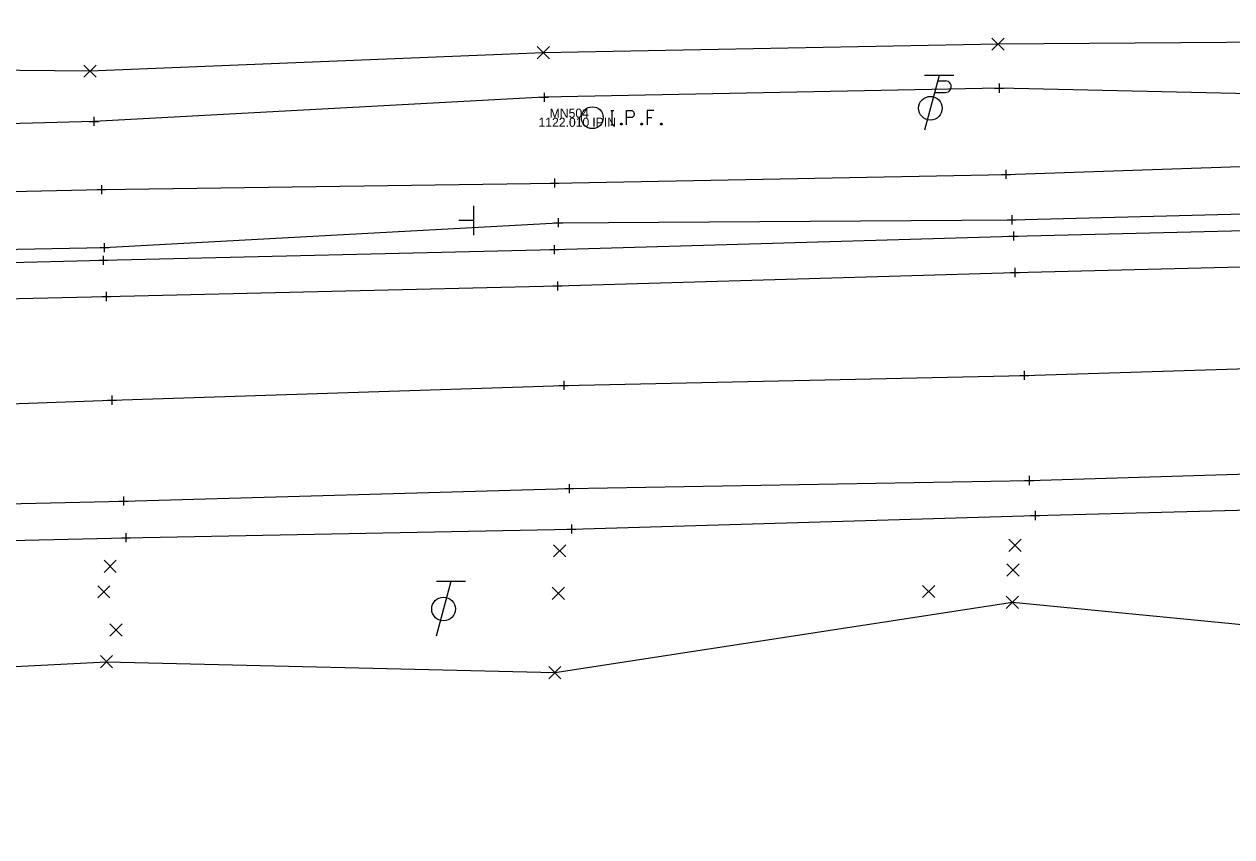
# Model space of a CAD drawing. Extents: x 2402028 to 2407435, y 498611 to 499105.
# Drawn here: x 2403678 to 2403810.6, y 498636.3 to 498725.5 of the extents above; entities that cross this region are included whole.
import ezdxf

# ---------------------------------------------------------------- set-up
doc = ezdxf.new("R2010")
doc.units = 0
for name, color, linetype in [('_CIVIL_CONSTRUCTION', 7, 'Continuous'), ('DR_X_Ditch', 7, 'Continuous'), ('PV_X_COP', 7, 'Continuous'), ('PV_X_EOP', 7, 'Continuous'), ('PV_X_Shoulder', 7, 'Continuous'), ('RW_X_CL_1000_Distances', 7, 'Continuous'), ('RW_X_CL_1000_Stations', 7, 'Continuous'), ('RW_X_CL_100_Bearings', 7, 'Continuous'), ('RW_X_CL_100_Cardinal_Points', 7, 'Continuous'), ('RW_X_CL_100_Stations', 7, 'Continuous'), ('RW_X_CL_500_Bearings', 7, 'Continuous'), ('RW_X_CL_500_Cardinal_Points', 7, 'Continuous'), ('RW_X_CL_500_Stations', 7, 'Continuous'), ('SV_X_Break_Lines', 7, 'Continuous'), ('SV_X_Terrain_Boundary', 7, 'Continuous')]:
    doc.layers.add(name, color=color, linetype=linetype)

msp = doc.modelspace()

# ---------------------------------------------------------------- linework, layer by layer
at = {"layer": 'DR_X_Ditch'}
msp.add_lwpolyline([(2403115.12, 498695.09), (2403139.28, 498697.03), (2403188.69, 498698.47), (2403237.26, 498698.52), (2403287.58, 498700.04), (2403338.31, 498701.02), (2403388.05, 498703.88), (2403439.2, 498702.19), (2403487.16, 498703.92), (2403540.55, 498705.7), (2403586.78, 498706.71), (2403636.91, 498706.23), (2403686.46, 498707.34), (2403736.22, 498708.05), (2403785.8, 498709.01), (2403836.25, 498710.7), (2403885.81, 498712.33), (2403935.71, 498713.55), (2403984.74, 498715.92), (2404035.79, 498716.24), (2404057.73, 498716.67)], dxfattribs=at)
at = {"layer": 'PV_X_COP'}
msp.add_lwpolyline([(2403339.4, 498675.07), (2403388.6, 498676.54), (2403439.52, 498678.71), (2403488.39, 498679.45), (2403539.43, 498681.45), (2403588.1, 498681.77), (2403637.7, 498682.43), (2403687.6, 498684.21), (2403737.23, 498685.84), (2403787.81, 498686.93), (2403836.99, 498688.45), (2403886.41, 498689.66), (2403936.62, 498690.72), (2403985.57, 498692.23), (2404036.54, 498693.02)], dxfattribs=at)
at = {"layer": 'PV_X_EOP'}
for points in [[(2403338.61, 498686.54), (2403387.34, 498688.53), (2403437.74, 498689.31), (2403487.06, 498690.99), (2403539.21, 498692.01), (2403587.62, 498693.45), (2403637.16, 498694.45), (2403686.98, 498695.6), (2403736.54, 498696.76), (2403786.79, 498698.23), (2403836.48, 498699.49), (2403886.02, 498700.75), (2403935.9, 498702.14), (2403985.32, 498703.46), (2404035.9, 498704.57), (2404085.81, 498705.89), (2404135.13, 498707.56), (2404185.41, 498708.59), (2404200.68, 498708.71)], [(2403340.13, 498663.91), (2403389.07, 498665.43), (2403439.65, 498666.68), (2403488.91, 498668.12), (2403539.47, 498669.35), (2403588.7, 498670.69), (2403639.11, 498671.99), (2403688.87, 498673.13), (2403737.83, 498674.5), (2403788.35, 498675.39), (2403837.8, 498676.88), (2403887.26, 498678.35), (2403937.03, 498679.79), (2403985.56, 498681.24), (2404036.04, 498682.2)]]:
    msp.add_lwpolyline(points, dxfattribs=at)
at = {"layer": 'PV_X_Shoulder'}
for p, q in [((2403786.63, 498702.23), (2403836.03, 498703.39)), ((2403736.19, 498700.75), (2403786.63, 498702.23)), ((2403686.65, 498699.57), (2403736.19, 498700.75)), ((2403636.62, 498698.35), (2403686.65, 498699.57))]:
    msp.add_line(p, q, dxfattribs=at)
msp.add_lwpolyline([(2403340.12, 498659.5), (2403389.1, 498660.69), (2403439.66, 498662.88), (2403489.16, 498663.97), (2403539.46, 498664.88), (2403589, 498666.58), (2403639.97, 498667.94), (2403689.14, 498669.11), (2403738.07, 498670.06), (2403789, 498671.54), (2403838.97, 498672.86), (2403888.69, 498674.59), (2403938.01, 498673.12), (2403986.56, 498676.91), (2404036.95, 498678.51)], dxfattribs=at)
at = {"layer": 'RW_X_CL_1000_Distances'}
for p, q in [((2403724.83, 498664.28), (2403723.22, 498658.28)), ((2403726.43, 498664.28), (2403723.23, 498664.28))]:
    msp.add_line(p, q, dxfattribs=at)
msp.add_circle((2403724.02, 498661.28), 1.3, dxfattribs=at)
at = {"layer": 'RW_X_CL_1000_Stations'}
for p, q in [((2403727.3, 498705.54), (2403727.3, 498702.34)), ((2403727.3, 498703.94), (2403725.7, 498703.94))]:
    msp.add_line(p, q, dxfattribs=at)
at = {"layer": 'RW_X_CL_100_Stations'}
for points in [[(2403742.38, 498716.03), (2403742.73, 498716.03)], [(2403742.55, 498714.43), (2403742.55, 498716.03)], [(2403744.12, 498714.43), (2403744.12, 498716.03), (2403744.65, 498716.03), (2403744.7, 498716.01), (2403744.78, 498715.99), (2403744.81, 498715.96), (2403744.85, 498715.94), (2403744.89, 498715.87), (2403744.92, 498715.81), (2403744.95, 498715.71), (2403744.95, 498715.56), (2403744.94, 498715.51), (2403744.91, 498715.43), (2403744.87, 498715.35), (2403744.82, 498715.31), (2403744.79, 498715.28), (2403744.74, 498715.26), (2403744.65, 498715.24), (2403744.12, 498715.24)], [(2403747.13, 498716.03), (2403746.37, 498716.03), (2403746.37, 498714.43)], [(2403743.51, 498714.64), (2403743.57, 498714.64), (2403743.6, 498714.61), (2403743.63, 498714.56), (2403743.63, 498714.5), (2403743.6, 498714.45), (2403743.57, 498714.43), (2403743.51, 498714.43), (2403743.48, 498714.45), (2403743.45, 498714.5), (2403743.45, 498714.56), (2403743.48, 498714.61), (2403743.51, 498714.64)], [(2403745.76, 498714.64), (2403745.82, 498714.64), (2403745.85, 498714.61), (2403745.88, 498714.56), (2403745.88, 498714.5), (2403745.85, 498714.45), (2403745.82, 498714.43), (2403745.76, 498714.43), (2403745.73, 498714.45), (2403745.7, 498714.5), (2403745.7, 498714.56), (2403745.73, 498714.61), (2403745.76, 498714.64)], [(2403746.37, 498715.24), (2403746.91, 498715.24)], [(2403747.91, 498714.64), (2403747.97, 498714.64), (2403748, 498714.61), (2403748.03, 498714.56), (2403748.03, 498714.5), (2403748, 498714.45), (2403747.97, 498714.43), (2403747.91, 498714.43), (2403747.88, 498714.45), (2403747.85, 498714.5), (2403747.85, 498714.56), (2403747.88, 498714.61), (2403747.91, 498714.64)], [(2403742.38, 498714.43), (2403742.73, 498714.43)]]:
    msp.add_lwpolyline(points, dxfattribs=at)
msp.add_circle((2403740.36, 498715.23), 1.2, dxfattribs=at)
at = {"layer": 'RW_X_CL_500_Bearings'}
for p, q in [((2403785.05, 498718.98), (2403785.05, 498717.98)), ((2403734.56, 498717.48), (2403735.56, 498717.48)), ((2403735.06, 498717.98), (2403735.06, 498716.98)), ((2403735.06, 498717.48), (2403735.06, 498717.48)), ((2403784.55, 498718.48), (2403785.55, 498718.48)), ((2403785.05, 498718.48), (2403785.05, 498718.48)), ((2403685.11, 498714.83), (2403686.11, 498714.83)), ((2403685.61, 498715.33), (2403685.61, 498714.33)), ((2403685.61, 498714.83), (2403685.61, 498714.83)), ((2403785.8, 498709.51), (2403785.8, 498708.51)), ((2403735.72, 498708.05), (2403736.72, 498708.05)), ((2403736.22, 498708.55), (2403736.22, 498707.55)), ((2403736.22, 498708.05), (2403736.22, 498708.05)), ((2403785.3, 498709.01), (2403786.3, 498709.01)), ((2403785.8, 498709.01), (2403785.8, 498709.01)), ((2403685.96, 498707.34), (2403686.96, 498707.34)), ((2403686.46, 498707.84), (2403686.46, 498706.84)), ((2403686.46, 498707.34), (2403686.46, 498707.34)), ((2403736.62, 498704.2), (2403736.62, 498703.2)), ((2403785.93, 498704.02), (2403786.93, 498704.02)), ((2403786.43, 498704.52), (2403786.43, 498703.52)), ((2403786.43, 498704.02), (2403786.43, 498704.02)), ((2403736.12, 498703.7), (2403737.12, 498703.7)), ((2403736.62, 498703.7), (2403736.62, 498703.7)), ((2403786.63, 498702.73), (2403786.63, 498701.73)), ((2403686.76, 498701.46), (2403686.76, 498700.46)), ((2403786.13, 498702.23), (2403787.13, 498702.23)), ((2403786.63, 498702.23), (2403786.63, 498702.23)), ((2403686.26, 498700.96), (2403687.26, 498700.96)), ((2403686.65, 498700.07), (2403686.65, 498699.07)), ((2403686.76, 498700.96), (2403686.76, 498700.96)), ((2403735.69, 498700.75), (2403736.69, 498700.75)), ((2403736.19, 498701.25), (2403736.19, 498700.25)), ((2403736.19, 498700.75), (2403736.19, 498700.75)), ((2403686.15, 498699.57), (2403687.15, 498699.57)), ((2403686.65, 498699.57), (2403686.65, 498699.57)), ((2403786.79, 498698.73), (2403786.79, 498697.73)), ((2403786.29, 498698.23), (2403787.29, 498698.23)), ((2403786.79, 498698.23), (2403786.79, 498698.23)), ((2403686.98, 498696.1), (2403686.98, 498695.1)), ((2403736.04, 498696.76), (2403737.04, 498696.76)), ((2403736.54, 498697.26), (2403736.54, 498696.26)), ((2403736.54, 498696.76), (2403736.54, 498696.76)), ((2403686.48, 498695.6), (2403687.48, 498695.6)), ((2403686.98, 498695.6), (2403686.98, 498695.6)), ((2403787.31, 498686.93), (2403788.31, 498686.93)), ((2403787.81, 498687.43), (2403787.81, 498686.43)), ((2403787.81, 498686.93), (2403787.81, 498686.93)), ((2403736.73, 498685.84), (2403737.73, 498685.84)), ((2403737.23, 498686.34), (2403737.23, 498685.34)), ((2403737.23, 498685.84), (2403737.23, 498685.84)), ((2403687.1, 498684.21), (2403688.1, 498684.21)), ((2403687.6, 498684.71), (2403687.6, 498683.71)), ((2403687.6, 498684.21), (2403687.6, 498684.21)), ((2403737.83, 498675), (2403737.83, 498674)), ((2403787.85, 498675.39), (2403788.85, 498675.39)), ((2403788.35, 498675.89), (2403788.35, 498674.89)), ((2403788.35, 498675.39), (2403788.35, 498675.39)), ((2403688.87, 498673.63), (2403688.87, 498672.63)), ((2403737.33, 498674.5), (2403738.33, 498674.5)), ((2403737.83, 498674.5), (2403737.83, 498674.5)), ((2403688.37, 498673.13), (2403689.37, 498673.13)), ((2403688.87, 498673.13), (2403688.87, 498673.13)), ((2403788.5, 498671.54), (2403789.5, 498671.54)), ((2403789, 498672.04), (2403789, 498671.04)), ((2403789, 498671.54), (2403789, 498671.54)), ((2403689.14, 498669.61), (2403689.14, 498668.61)), ((2403737.57, 498670.06), (2403738.57, 498670.06)), ((2403738.07, 498670.56), (2403738.07, 498669.56)), ((2403738.07, 498670.06), (2403738.07, 498670.06)), ((2403688.64, 498669.11), (2403689.64, 498669.11)), ((2403689.14, 498669.11), (2403689.14, 498669.11))]:
    msp.add_line(p, q, dxfattribs=at)
at = {"layer": 'RW_X_CL_500_Cardinal_Points'}
for p, q in [((2403778.46, 498719.88), (2403776.85, 498713.88)), ((2403780.06, 498719.88), (2403776.86, 498719.88)), ((2403778.3, 498719.27), (2403779.15, 498719.27)), ((2403777.96, 498718), (2403779.15, 498718))]:
    msp.add_line(p, q, dxfattribs=at)
msp.add_circle((2403777.5, 498716.27), 1.3, dxfattribs=at)
msp.add_arc((2403779.16, 498718.64), 0.638, 268.8767, 91.1233, dxfattribs=at)
at = {"layer": 'RW_X_CL_500_Stations'}
for p, q in [((2403784.26, 498722.64), (2403785.59, 498723.98)), ((2403784.26, 498723.98), (2403785.59, 498722.64)), ((2403734.31, 498721.7), (2403735.65, 498723.04)), ((2403734.31, 498723.04), (2403735.65, 498721.7)), ((2403684.51, 498719.67), (2403685.85, 498721.01)), ((2403684.51, 498721.01), (2403685.85, 498719.67)), ((2403736.11, 498667.01), (2403737.45, 498668.34)), ((2403736.11, 498668.34), (2403737.45, 498667.01)), ((2403786.13, 498667.59), (2403787.46, 498668.93)), ((2403786.13, 498668.93), (2403787.46, 498667.59)), ((2403686.73, 498665.29), (2403688.07, 498666.63)), ((2403686.73, 498666.63), (2403688.07, 498665.29)), ((2403785.91, 498664.89), (2403787.25, 498666.23)), ((2403785.91, 498666.23), (2403787.25, 498664.89)), ((2403686.05, 498662.5), (2403687.38, 498663.83)), ((2403686.05, 498663.83), (2403687.38, 498662.5)), ((2403735.96, 498662.33), (2403737.29, 498663.67)), ((2403735.96, 498663.67), (2403737.29, 498662.33)), ((2403776.65, 498662.53), (2403777.98, 498663.86)), ((2403776.65, 498663.86), (2403777.98, 498662.53)), ((2403785.83, 498661.34), (2403787.16, 498662.68)), ((2403785.83, 498662.68), (2403787.16, 498661.34)), ((2403687.38, 498658.3), (2403688.71, 498659.64)), ((2403687.38, 498659.64), (2403688.71, 498658.3)), ((2403686.34, 498654.82), (2403687.67, 498656.16)), ((2403686.34, 498656.16), (2403687.67, 498654.82)), ((2403735.57, 498653.62), (2403736.9, 498654.95)), ((2403735.57, 498654.95), (2403736.9, 498653.62))]:
    msp.add_line(p, q, dxfattribs=at)
at = {"layer": 'SV_X_Break_Lines'}
for points in [[(2404019.04, 498713.49), (2404033.84, 498711.06), (2404059.48, 498713.51), (2404061.23, 498716.75), (2404058.41, 498720.02), (2404035.5, 498720.85), (2403984.19, 498717.86), (2403935.32, 498717.7), (2403885.41, 498717.04), (2403835.4, 498717.35), (2403785.05, 498718.48), (2403735.06, 498717.48), (2403685.61, 498714.83), (2403635.75, 498713.46), (2403587.21, 498711.88)], [(2403337.63, 498692.95), (2403385.67, 498694.88), (2403436.95, 498695.07), (2403486.78, 498697.64), (2403538.09, 498697.36), (2403587.38, 498698.96), (2403637.26, 498700.04), (2403686.76, 498700.96), (2403736.62, 498703.7), (2403786.43, 498704.02), (2403835.95, 498705.28), (2403885.12, 498707.9), (2403935.66, 498709.22), (2403986.83, 498710.71), (2404005.79, 498712.51)]]:
    msp.add_lwpolyline(points, dxfattribs=at)
at = {"layer": 'SV_X_Terrain_Boundary'}
for points in [[(2404013.92, 498724.8), (2403983.78, 498725.5), (2403934.83, 498724.06), (2403835.07, 498723.66), (2403784.93, 498723.31), (2403734.98, 498722.37), (2403685.18, 498720.34), (2403634.9, 498720.82), (2403540.9, 498720.47), (2403442.1, 498718.56), (2403390.54, 498717.85), (2403340.67, 498716.01)], [(2403346.11, 498636.26), (2403438.36, 498646.02), (2403538.18, 498650.74), (2403589.85, 498649.52), (2403621.66, 498652.13), (2403687.01, 498655.49), (2403736.24, 498654.29), (2403786.5, 498662.01), (2403837.7, 498657.06), (2403883.46, 498651.52), (2403933.92, 498653.73), (2403937.33, 498653.02), (2403944.86, 498652.27), (2403985.55, 498656.18), (2404071.93, 498644.97)]]:
    msp.add_lwpolyline(points, dxfattribs=at)

# ---------------------------------------------------------------- texts
at = {"layer": '_CIVIL_CONSTRUCTION'}
msp.add_text('MN504', height=1, dxfattribs=at).set_placement((2403735.68, 498715.23))
at = {"layer": 'RW_X_CL_100_Bearings'}
msp.add_text('1122.010', height=1, dxfattribs=at).set_placement((2403734.45, 498714.23))
at = {"layer": 'RW_X_CL_100_Cardinal_Points'}
msp.add_text('IPIN', height=1, dxfattribs=at).set_placement((2403740.36, 498714.23))

doc.saveas('drawing.dxf')
